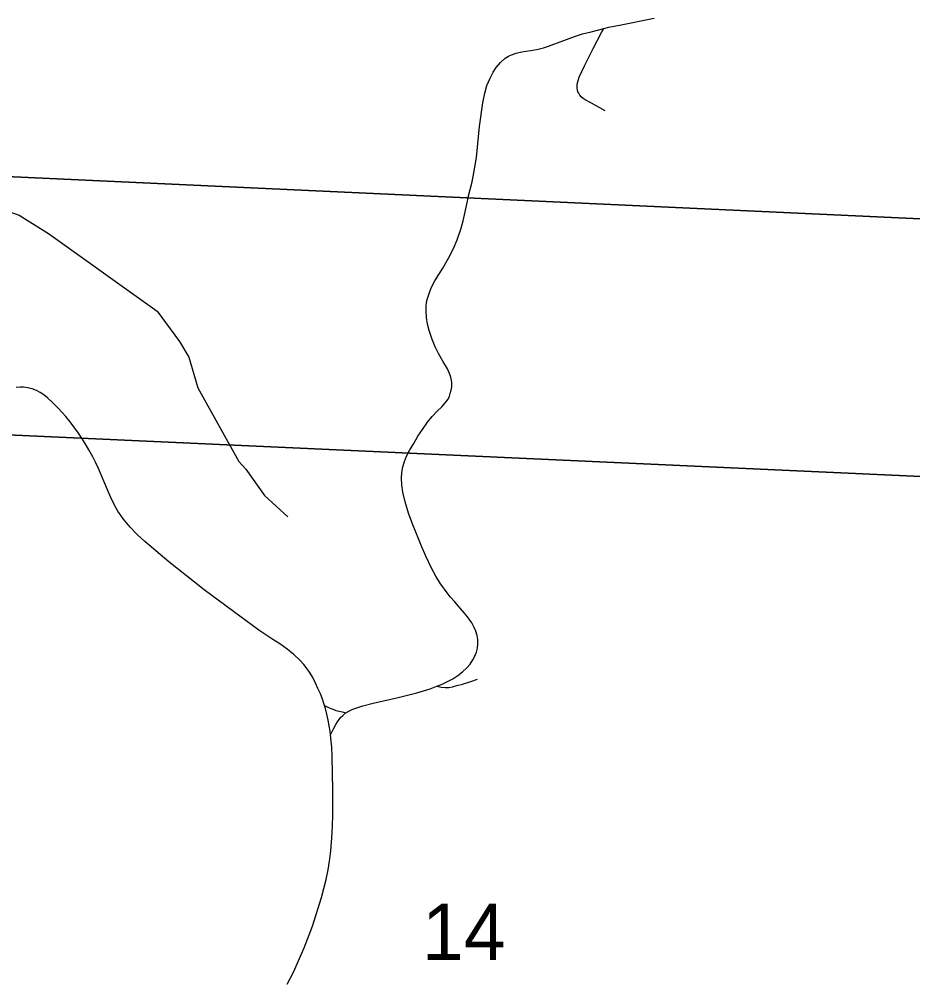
# Model space of a CAD drawing. Extents: x 0 to 34, y 0 to 22.
# Drawn here: x 4.072 to 4.739, y 14.692 to 15.408 of the extents above; entities that cross this region are included whole.
import ezdxf

# ---------------------------------------------------------------- set-up
doc = ezdxf.new("R2010")
doc.units = 0
for name, color, linetype in [('GM_X_County_Road', 7, 'Continuous'), ('GM_X_Minor_River', 7, 'Continuous'), ('GM_X_Section', 7, 'Continuous'), ('GM_X_Section_Text', 7, 'Continuous'), ('GM_X_State_Route', 7, 'Continuous'), ('GM_X_Township_Road', 7, 'Continuous')]:
    doc.layers.add(name, color=color, linetype=linetype)

msp = doc.modelspace()

# ---------------------------------------------------------------- linework, layer by layer
at = {"layer": 'GM_X_County_Road'}
for points in [[(4.3042, 14.87418), (4.30636, 14.87859), (4.30797, 14.88189), (4.30922, 14.88387), (4.31061, 14.8857), (4.31166, 14.88706), (4.31319, 14.88865), (4.31554, 14.89062), (4.31789, 14.89197), (4.32087, 14.89335), (4.32295, 14.89418), (4.3282, 14.89593), (4.336, 14.89794), (4.35469, 14.90209), (4.36861, 14.90557), (4.37843, 14.90855), (4.38351, 14.91046), (4.38681, 14.91171), (4.39095, 14.91366), (4.39538, 14.91601), (4.39904, 14.91843), (4.40251, 14.92115), (4.40573, 14.92415), (4.40825, 14.92698), (4.41041, 14.93011), (4.41159, 14.93235), (4.41298, 14.93588), (4.41381, 14.93895), (4.41411, 14.94211), (4.414, 14.94528), (4.41349, 14.94841), (4.41261, 14.95146), (4.4114, 14.95439), (4.40955, 14.95769), (4.40627, 14.96229), (4.40394, 14.96521), (4.39655, 14.9736), (4.39371, 14.97688), (4.38958, 14.98218), (4.38784, 14.98458), (4.38621, 14.98694), (4.38264, 14.99265), (4.37946, 14.99861), (4.3753, 15.0075), (4.3721, 15.01488), (4.36991, 15.02002), (4.36545, 15.03092), (4.36232, 15.03966), (4.35983, 15.04796), (4.35814, 15.05517), (4.35731, 15.06065), (4.35707, 15.06554), (4.35734, 15.06981), (4.35806, 15.07401), (4.35923, 15.0781), (4.36083, 15.08204), (4.36341, 15.08686), (4.36618, 15.09158), (4.36935, 15.09686), (4.37267, 15.10204), (4.37655, 15.1075), (4.38005, 15.11171), (4.38377, 15.1156), (4.38722, 15.11885), (4.38998, 15.12197), (4.3918, 15.12462), (4.39288, 15.12677), (4.39345, 15.12868), (4.3942, 15.13132), (4.39459, 15.13368), (4.39456, 15.13733), (4.39386, 15.14092), (4.39288, 15.14381), (4.3913, 15.14711), (4.3879, 15.15289), (4.38458, 15.1587), (4.38218, 15.16366), (4.37966, 15.16994), (4.37768, 15.17578), (4.37649, 15.18056), (4.3757, 15.18541), (4.37537, 15.19031), (4.3755, 15.19396), (4.37574, 15.19638), (4.37626, 15.19879), (4.37765, 15.20348), (4.37952, 15.20799), (4.38206, 15.21288), (4.38779, 15.22237), (4.39221, 15.22984), (4.39588, 15.23706), (4.39857, 15.24339), (4.40165, 15.25222), (4.4031, 15.25765), (4.40627, 15.27221), (4.40692, 15.27525), (4.40969, 15.28673), (4.41115, 15.29343), (4.41193, 15.29898), (4.4129, 15.30472), (4.41534, 15.32792), (4.41771, 15.34552), (4.41936, 15.35281), (4.42085, 15.3584), (4.42314, 15.36404), (4.42539, 15.36834), (4.42777, 15.37185), (4.43082, 15.37562), (4.43443, 15.37878), (4.43699, 15.38036), (4.43914, 15.38141), (4.44257, 15.38264), (4.44672, 15.38362), (4.45651, 15.38504), (4.45896, 15.3856), (4.46306, 15.38666), (4.46673, 15.38784), (4.48204, 15.39363), (4.48688, 15.39535), (4.49222, 15.397), (4.49845, 15.39864), (4.50789, 15.40097), (4.51176, 15.40192), (4.52082, 15.40378), (4.54547, 15.4088)], [(4.29964, 14.89614), (4.30273, 14.89459), (4.30512, 14.89356), (4.30649, 14.893), (4.30816, 14.89244), (4.31052, 14.89188), (4.31276, 14.89132), (4.31554, 14.89062)]]:
    msp.add_lwpolyline(points, dxfattribs=at)
at = {"layer": 'GM_X_Minor_River'}
msp.add_lwpolyline([(3.7646, 15.33419), (3.82657, 15.3588), (3.84661, 15.35931), (3.862, 15.35578), (3.9092, 15.32922), (3.94847, 15.31545), (3.97671, 15.29936), (4.00426, 15.28558), (4.07195, 15.26179), (4.09384, 15.24818), (4.17486, 15.19017), (4.19156, 15.16762), (4.19839, 15.15601), (4.20525, 15.13301), (4.23572, 15.07813), (4.24083, 15.07227), (4.25498, 15.05283), (4.27226, 15.03672)], dxfattribs=at)
at = {"layer": 'GM_X_Section'}
for points in [[(3.93387, 15.56017), (4.383, 15.53841), (4.90656, 15.51304), (4.88898, 15.25227), (3.91727, 15.29734)], [(4.88898, 15.25227), (4.95802, 15.24907), (4.94642, 15.05765), (3.90513, 15.1052), (3.91727, 15.29734)], [(3.90513, 15.1052), (4.94642, 15.05765), (4.92002, 14.61934), (3.87764, 14.6701)]]:
    msp.add_lwpolyline(points, close=True, dxfattribs=at)
at = {"layer": 'GM_X_State_Route'}
msp.add_lwpolyline([(4.27188, 14.68816), (4.27639, 14.6971), (4.28438, 14.71535), (4.29065, 14.73158), (4.29738, 14.75291), (4.30081, 14.76628), (4.30229, 14.77348), (4.30363, 14.78167), (4.30431, 14.78774), (4.30483, 14.79407), (4.30526, 14.80091), (4.3056, 14.80724), (4.30577, 14.81336), (4.30585, 14.83295), (4.30534, 14.85813), (4.30502, 14.865), (4.3047, 14.86942), (4.3042, 14.87418), (4.3038, 14.87705), (4.30322, 14.88084), (4.30239, 14.8852), (4.30142, 14.88969), (4.30034, 14.89379), (4.29964, 14.89614), (4.29918, 14.89771), (4.2979, 14.90149), (4.29655, 14.90489), (4.29476, 14.90887), (4.29296, 14.91278), (4.29084, 14.91689), (4.28887, 14.92023), (4.28673, 14.92348), (4.28429, 14.92665), (4.2813, 14.92989), (4.27669, 14.93417), (4.27181, 14.93811), (4.2662, 14.9421), (4.261, 14.94545), (4.25065, 14.95238), (4.23169, 14.96615), (4.20997, 14.98232), (4.18339, 15.00322), (4.16556, 15.01832), (4.15991, 15.02365), (4.15471, 15.02903), (4.14977, 15.035), (4.14554, 15.04096), (4.14265, 15.04597), (4.14015, 15.05129), (4.13778, 15.05687), (4.13105, 15.07294), (4.12891, 15.07756), (4.12686, 15.08158), (4.12395, 15.08671), (4.1211, 15.09144), (4.11857, 15.09543), (4.11609, 15.09919), (4.11275, 15.1039), (4.1099, 15.10776), (4.10668, 15.1116), (4.10129, 15.11754), (4.09701, 15.12181), (4.0929, 15.12549), (4.09017, 15.12771), (4.0876, 15.12942), (4.0847, 15.13096), (4.08145, 15.13224), (4.0782, 15.1331), (4.07511, 15.13353), (4.07255, 15.13362), (4.06973, 15.13336)], dxfattribs=at)
at = {"layer": 'GM_X_Township_Road'}
for points in [[(4.50909, 15.33973), (4.49878, 15.34521), (4.49417, 15.34785), (4.49255, 15.34887), (4.49113, 15.35015), (4.49008, 15.3514), (4.48924, 15.35269), (4.48867, 15.35381), (4.48834, 15.355), (4.48805, 15.35652), (4.48808, 15.35783), (4.48817, 15.35954), (4.48859, 15.36132), (4.48968, 15.36469), (4.49362, 15.37315), (4.50004, 15.38599), (4.50632, 15.39796), (4.50789, 15.40097)], [(4.38351, 14.91046), (4.38676, 14.90982), (4.38968, 14.90953), (4.39234, 14.90965), (4.39508, 14.9101), (4.39841, 14.91091), (4.40266, 14.91211), (4.40868, 14.91406), (4.4137, 14.9157)]]:
    msp.add_lwpolyline(points, dxfattribs=at)

# ---------------------------------------------------------------- texts
at = {"layer": 'GM_X_Section_Text'}
msp.add_text('14', height=0.041856, rotation=0.00001, dxfattribs=at).set_placement((4.37243, 14.70635))

doc.saveas('drawing.dxf')
